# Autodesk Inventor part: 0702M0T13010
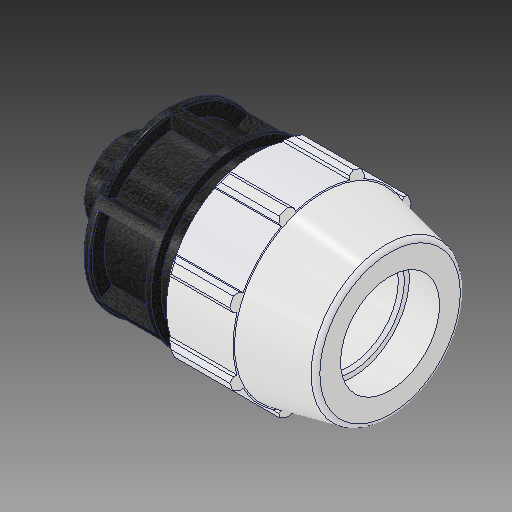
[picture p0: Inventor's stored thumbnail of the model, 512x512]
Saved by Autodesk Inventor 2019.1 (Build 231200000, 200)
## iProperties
Created: 2017-02
Part Number: 0702M0T13010
Material: PVC-Piping
Description: PLASSON MALE ADAPTOR 1 1/4'' - 1''M
Document SubType Name: Modeling
Designer: KIM
Mass: 92.6774 g
Surface Area: 199.44 cm^2
Volume: 66.1981 cm^3
Density: 1.4 g/cm^3
Appearance: PTFE
Author: KIM
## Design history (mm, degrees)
derived "0702M0T.ipt"
feature "Solid1::0702M0T.ipt"
tag "TaggingFeature1"
body "Solid1"
other parameters: "d2" = 42.1, "d4" = 16.29229, "d5" = 28.5115, "d7" = 82.042, "d8" = 61.5315, "d9" = 16.29229, "d11" = 3.25846, "d12" = 65.6336, "d13" = 120 deg, "d14" = 63.15, "d15" = 12 deg, "d16" = 73.8378, "d18" = 2.105, "d19" = 35 deg, "d20" = 17.5 deg, "d21" = 76.29906, "d23" = 0, "d25" = 360 deg, "d27" = 1.64084, "d34" = 4.1021, "d36" = 0, "d42" = 28.5115, "d43" = 2.46126, "d46" = 1.263, "d51" = 114.046, "d52" = 20.066, "d53" = 0.842, "d55" = 360 deg, "d57" = 33.249, "d58" = 23.2743, "d59" = 22.8092, "d61" = 25.146, "d_" = 42.1, "E_" = 82.042, "H_" = 114.046, "l_" = 86.106, "l_2" = 20.066, "G_" = 33.249
